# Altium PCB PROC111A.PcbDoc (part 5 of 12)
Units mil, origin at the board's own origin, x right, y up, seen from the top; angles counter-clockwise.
Board outline 7700 x 2300 mil, 6 copper layers (Top Layer, GND 1, SIG 1, SIG 2, GND 2, Bottom Layer), stack 61.062 mil thick; 841 components, 632 nets, 2914 pads, 1627 vias.
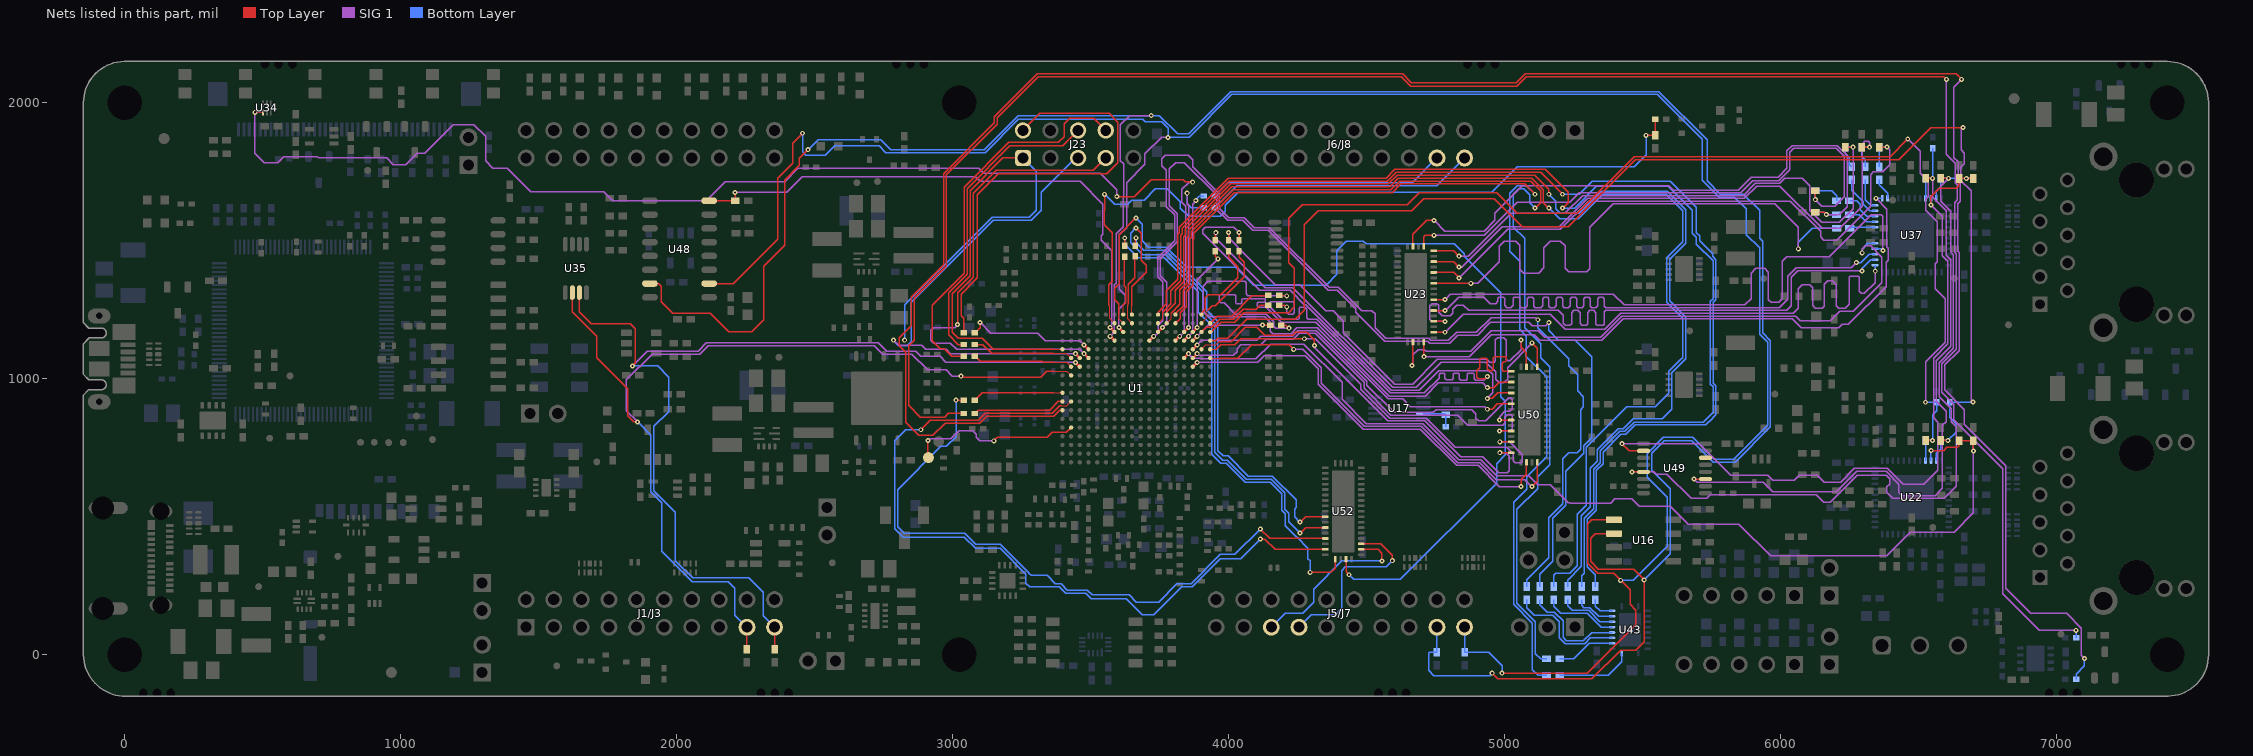
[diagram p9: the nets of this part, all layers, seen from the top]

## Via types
v1: diameter 18, hole 8, Top Layer to Bottom Layer, tented both sides, 1523 vias
v2: diameter 19.68, hole 7.87, Top Layer to Bottom Layer, tented both sides, 104 vias

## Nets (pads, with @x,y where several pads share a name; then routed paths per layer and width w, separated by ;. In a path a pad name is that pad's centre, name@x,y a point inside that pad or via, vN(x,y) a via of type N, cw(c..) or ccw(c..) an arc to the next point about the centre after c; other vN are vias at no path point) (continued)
AM263_EQEP0_A: R328.1 U1.B14 | length 3715.4
  Top Layer w5.3: U1.B14@3806.58,1201.3 3823.55,1218.27 3823.55,1238.81 3845.2,1260.46 3845.2,1314.6 3869.86,1339.27 3869.86,1503.63 3873.69,1507.46 3873.69,1528.02 4019.83,1674.16 4591.58,1674.16 4623.38,1705.96 5072.2,1705.96 v1(5109.51,1668.66)
  Bottom Layer w5.3: v1(5109.51,1668.66) 5078.17,1700 5045,1700 5017.5,1672.5 5017.5,1462 5054.25,1425.25 5054.25,1178.63 5078.38,1154.5 5078.38,1080 5151.68,1006.71 5151.68,717.97 5078.7,645 5078.7,600 5032.22,553.52 5032.22,182.77 5100,114.99 5100,-53.62 5121.38,-75 R328.1@5151.38,-75
AM263_EQEP0_A_R: R328.2 U43.1 | length 277.2
  Bottom Layer w5.3: R328.2@5198.62,-75 5374.13,-75 5424.13,-25 U43.1@5424.13,5.98
AM263_EQEP0_B: R329.1 U1.A14 | length 3726.7
  Top Layer w5.3: U1.A14@3806.58,1232.8 3806.58,1234.99 3834.6,1263.01 3834.6,1318.99 3859.26,1343.66 3859.26,1508.02 3863.09,1511.85 3863.09,1532.41 4015.44,1684.76 4587.18,1684.76 4618.98,1716.56 5093.44,1716.56 5129.38,1680.62 5129.38,1638.54 v1(5109.51,1618.66)
  Bottom Layer w5.3: v1(5109.51,1618.66) 5089.98,1638.18 5089.98,1666.52 5068.32,1688.18 5051.42,1688.18 5031.5,1668.26 5031.5,1549.88 5072.5,1508.88 5072.5,1184.24 5129.52,1127.22 5129.52,1076.22 5162.28,1043.47 5162.28,688.75 5118.53,645 5118.53,602.23 5042.82,526.53 5042.82,187.16 5110.6,119.38 5110.6,116.68 5111.17,116.11 5111.17,3.83 5129.91,-14.91 R329.1@5151.38,-14.91
AM263_EQEP0_B_R: R329.2 U43.3 | length 213.4
  Bottom Layer w5.3: R329.2@5198.62,-14.91 5249.09,-14.91 5305.41,41.41 U43.3@5388.7,41.41
AM263_EQEP0_INDEX: R330.1 U1.D11 | length 3627.9
  Top Layer w10: U1.D11@3712.09,1138.31 v1(3727.84,1154.06)
  SIG 1 w4.75: v1(3727.84,1154.06) 3731.43,1154.06 3736.19,1158.82 3736.38,1158.82 3743.69,1166.13 3743.69,1193.54 3760.09,1209.94 3760.09,1264.29 3760.09,1351.49 3741.88,1369.7 3741.88,1438.9 3803.46,1500.48 3803.46,1594.32 3773.57,1624.21 3773.57,1756.43 3757.97,1772.03 3757.97,1797.66 3769.66,1809.35 3852.94,1809.35 3854.33,1807.96 3868.98,1793.31 3868.98,1768.05 3966.01,1671.01 3966.01,1617.44 3999.54,1583.91 4055.16,1583.91 4091.4,1547.68 4146.89,1547.68 4363.67,1330.91 4396.84,1330.91 4479.55,1248.2 4480.94,1246.81 4507.02,1246.81 cw(c4509.76,1227.76) 4512.51,1246.81 4517.93,1246.81 4519.32,1245.42 4529.81,1234.94 4529.81,1185.4 4568.33,1146.87 4724.31,1146.87 4731.78,1139.4 4795.95,1139.4 4825.26,1168.71 4897.28,1168.71 4950.07,1221.5 5112.15,1221.5 v1(5119.65,1214)
  Bottom Layer w5.3: R330.1@5079.44,247.13 5079.44,271.97 5159.5,352.03 5159.5,496.09 5209.88,546.47 5209.88,710.04 5232.23,732.4 5262.4,732.4 5274.59,744.59 5274.59,887.74 5285,898.15 5285,934.57 5263.5,956.07 5263.5,1015.36 5232.23,1046.63 5232.23,1072.76 5119.65,1185.35 v1(5119.65,1214)
AM263_EQEP0_INDEX_R: R330.2 U43.4 | length 435.2
  Bottom Layer w5.3: R330.2@5079.44,199.89 5079.44,170.8 5107.23,143 5174.19,143 5197.18,120.02 5197.18,62.16 5219.34,40 5289.01,40 5310.1,61.1 U43.4@5388.7,61.1
AM263_EQEP0_STROBE: R331.1 U1.C12 | length 3521.5
  Top Layer w10: U1.C12@3743.59,1169.8 v1(3759.34,1185.55)
  SIG 1 w4.75: v1(3759.34,1185.55) 3775.83,1202.05 3775.83,1349.95 3751.93,1373.86 3751.93,1434.73 3813.51,1496.32 3813.51,1598.48 3784.21,1627.78 3784.21,1760.42 3807.19,1783.4 3839.42,1783.4 3955.96,1666.85 3955.96,1613.28 3995.37,1573.86 4051,1573.86 4087.23,1537.63 4142.73,1537.63 4359.5,1320.86 4392.68,1320.86 4460.15,1253.39 4460.15,1240.84 4564.17,1136.82 4720.15,1136.82 4727.61,1129.35 4800.12,1129.35 4829.43,1158.66 4901.44,1158.66 4947.78,1205 5086.5,1205 5099,1192.5 5148.5,1192.5 v1(5159.5,1203.5)
  Bottom Layer w5.3: R331.1@5127.45,247.13 5127.45,292.72 5172.88,338.15 5172.88,494.48 5220.48,542.08 5220.48,665.42 5285.19,730.14 5285.19,756.89 5315.38,787.08 5315.38,1079.97 5255.35,1140 5194.5,1140 5159.5,1175 v1(5159.5,1203.5)
AM263_EQEP0_STROBE_R: R331.2 U43.5 | length 382
  Bottom Layer w5.3: R331.2@5127.45,199.89 5127.45,181.1 5153.54,155 5180,155 5211.17,123.83 5211.17,63.16 5223.5,50.83 5284.84,50.83 5314.8,80.78 U43.5@5388.7,80.78
AM263_EQEP2_A: R332.1 U1.B13 | length 4081.1
  Top Layer w4: U1.B13@3775.09,1201.3 3790.83,1217.05 3790.83,1237.93
  Top Layer w5.3: 3790.83,1237.93 3822.4,1269.5 3822.4,1321.79 3847.29,1346.68 3847.29,1511.04 3852.49,1516.24 3852.49,1536.8 4011.05,1695.36 4582.79,1695.36 4614.59,1727.16 5097.84,1727.16 5139.98,1685.02 5139.98,1638.18 v1(5159.51,1618.66)
  Bottom Layer w5.3: v1(5159.51,1618.66) 5160.4,1618.66 5199.66,1579.4 5265.42,1579.4 5354.22,1668.2 5584.35,1668.2 5644.52,1608.03 5644.52,1496.1 5586.23,1437.8 5586.23,1277.78 5644.52,1219.49 5644.52,1076.91 5637.86,1070.25 5637.86,1069.97 5594.4,1026.5 5594.4,947.83 5544.68,898.11 5441.4,898.11 5295.79,752.5 5295.79,541.88 5263.06,509.15 5263.06,323.25 5234.78,294.97 5185.01,294.97 5177.45,287.4 R332.1@5177.45,247.13
AM263_EQEP2_A_R: R332.2 U43.6 | length 266.9
  Bottom Layer w5.3: R332.2@5177.45,199.89 5177.45,175.16 5202.6,150 5299.54,150 5349.07,100.47 U43.6@5388.7,100.47
AM263_EQEP2_B: R333.1 U1.A13 | length 4039
  Top Layer w4: U1.A13@3775.09,1232.8 3775.09,1242.08
  Top Layer w5.3: 3775.09,1242.08 3806.58,1273.58 3806.58,1320.96 3836.69,1351.07 3836.69,1515.43 3841.89,1520.63 3841.89,1541.2 4006.66,1705.96 4578.4,1705.96 4610.2,1737.76 5108.54,1737.76 5159.51,1686.79 v1(5159.51,1668.66)
  Bottom Layer w5.3: v1(5159.51,1668.66) 5185,1643.17 5185,1615.56 5201.42,1599.14 5270.16,1599.14 5349.83,1678.8 5588.74,1678.8 5655.12,1612.42 5655.12,1491.71 5596.83,1433.41 5596.83,1282.17 5655.12,1223.88 5655.12,1072.24 5605,1022.11 5605,888.76 5571.24,855 5464.98,855 5429.67,819.69 5411.6,819.69 5334.84,742.93 5334.84,700.53 5310,675.69 5310,536.96 5276.85,503.81 5276.85,319.93 5227.45,270.52 R333.1@5227.45,247.13
AM263_EQEP2_B_R: R333.2 U43.7 | length 207.4
  Bottom Layer w5.3: R333.2@5227.45,199.89 5227.45,177.55 5244.4,160.6 5303.93,160.6 5344.38,120.15 U43.7@5388.7,120.15
AM263_EQEP2_INDEX: R334.1 U1.A12 | length 4240.1
  Top Layer w5.3: U1.A12@3743.59,1232.8 3743.59,1241.19 3773.85,1271.45 3773.85,1318.2 3815.49,1359.85 3815.49,1524.21 3820.69,1529.41 3820.69,1549.98 3997.88,1727.16 4569.62,1727.16 4601.42,1758.96 5146.81,1758.96 5229.48,1676.3 5229.48,1638.63 v1(5209.51,1618.66)
  Bottom Layer w5.3: v1(5209.51,1618.66) 5252.86,1618.66 5331.51,1697.31 5592.69,1697.31 5680,1610 5680,1526.8 5694.52,1512.28 5694.52,1487.83 5754.52,1427.83 5754.52,1290.9 5745.28,1281.66 5745.28,979.8 5754.52,970.56 5754.52,878.84 5719.05,843.37 5468.34,843.37 5434.06,809.09 5415.99,809.09 5345.44,738.54 5345.44,696.14 5321.45,672.15 5321.45,528.97 5287.45,494.97 5287.45,296.35 5278.06,286.97 R334.1@5278.06,247.13
AM263_EQEP2_INDEX_R: R334.2 U43.8 | length 147.2
  Bottom Layer w5.3: R334.2@5278.06,199.89 5278.06,180 5286.86,171.2 5308.32,171.2 5339.68,139.84 U43.8@5388.7,139.84
AM263_EQEP2_STROBE: R335.1 U1.B12 | length 4195.6
  Top Layer w4: U1.B12@3743.59,1201.3 3760,1217.71 3760,1235
  Top Layer w5.3: 3760,1235 3760,1241.99 3790,1271.99 3790,1319.37 3826.09,1355.46 3826.09,1519.82 3831.29,1525.02 3831.29,1545.59 4002.27,1716.56 4574.01,1716.56 4605.81,1748.36 5129.8,1748.36 v1(5209.51,1668.66)
  Bottom Layer w5.3: v1(5209.51,1668.66) 5270.14,1668.66 5316.48,1715 5600,1715 5693.5,1621.5 5693.5,1529.5 5705.48,1517.52 5705.48,1500.65 5753.33,1452.8 5753.33,1444.01 5765.12,1432.22 5765.12,1286.51 5755.88,1277.27 5755.88,984.19 5765.12,974.95 5765.12,869.89 5753.33,858.1 5753.33,857.79 5728.31,832.77 5472.73,832.77 5438.45,798.49 5420.38,798.49 5356.04,734.15 5356.04,691.75 5332.05,667.76 5332.05,524.58 5298.05,490.58 5298.05,319.67 5328.01,289.71 R335.1@5328.01,247.13
AM263_EQEP2_STROBE_R: R335.2 U43.9 | length 91.1
  Bottom Layer w5.3: R335.2@5328.01,199.89 5328.01,176.51 5345,159.52 U43.9@5388.7,159.52
AM263_EXT_REFCLK0: TP2.1 U1.P2 | length 637.5
  Top Layer w5.3: v1(2910,776.1) 2910,716.22 TP2.1@2911.79,714.43 ; v1(3148.62,775.4) 3161.89,788.67 3343.09,788.67 3360.79,806.37 3411.66,806.37 U1.P2@3428.63,823.35
  SIG 1 w5.3: v1(2910,776.1) 2915.9,782 2993.46,782 3022.83,811.37 3073.09,811.37 3084.52,799.94 3084.52,787.86 3096.99,775.4 v1(3148.62,775.4)
AM263_FSIRX1_CLK: J23.1 U1.E1 | length 2160.2
  Top Layer w4: 3365.64,1106.81 U1.E1@3397.13,1106.81
  Top Layer w5.3: J23.1@3254.17,1800 3181,1800 3063,1682 3063,1374 2997.98,1308.98 2997.98,1169.46 3020.54,1146.89 3105.82,1146.89 3145.9,1106.81 3365.64,1106.81
  Bottom Layer w5.3: v1(2825.61,1140) 2826.32,1140.71 2826.32,1268.09 3143.73,1585.5 3277.61,1585.5 3302.05,1609.94 3302.05,1752.13 J23.1@3254.17,1800
AM263_FSIRX1_DATA0: J23.5 U1.F3 | length 1782.6
  Top Layer w10: v1(3444.38,1091.06) U1.F3@3460.12,1075.32
  SIG 1 w4.75: v1(2785,1140) 2803.56,1121.44 2816.94,1121.44 2817.63,1120.75 2888.25,1120.75 2902.5,1106.5 2975.39,1106.5 2990.82,1091.06 v1(3444.38,1091.06)
  Bottom Layer w5.3: v1(2785,1140) 2805,1120 2835,1120 2850,1135 2850,1276.78 3147.22,1574 3284,1574 3320,1610 3320,1675.78 3437.73,1793.5 3447.67,1793.5 J23.5@3454.17,1800
AM263_FSIRX1_DATA1: J23.7 U1.F4 | length 1770.2
  Top Layer w5.3: v1(3017.5,1197) 3017.5,1311.5 3073.6,1367.6 3073.6,1672 3157.1,1755.5 3509.67,1755.5 J23.7@3554.17,1800
  Top Layer w10: v1(3475.87,1091.06) U1.F4@3491.62,1075.32
  SIG 1 w4.75: v1(3017.5,1197) 3006.21,1185.71 2931.21,1185.71 2921,1175.5 2921,1140 2931.5,1129.5 2991,1129.5 3014.06,1106.44 3460.5,1106.44 v1(3475.87,1091.06)
AM263_FSITX1_CLK: J23.2 R54.1 | length 1615.8
  Top Layer w5.3: R54.1@3040,1167.26 3040,1219 3030,1229 3030,1306.5 3089,1365.5 3089,1667.6 3164.9,1743.5 3558.49,1743.5 3598.5,1783.5 3598.5,1930 3567,1961.5 3315.67,1961.5 J23.2@3254.17,1900
AM263_FSITX1_CLK_R: R54.2 U1.E4 | length 480.3
  Top Layer w5.3: R54.2@3079.37,1167.26 3081.34,1167.26 3099,1184.92 v1(3099,1204.5)
  Top Layer w10: v1(3475.87,1122.56) U1.E4@3491.62,1106.81
  SIG 1 w4.75: v1(3099,1204.5) 3138,1165.5 3308.5,1165.5 3335.5,1138.5 3366.64,1138.5 3459.93,1138.5 3475.37,1123.06 v1@3476.77,1123.06
AM263_FSITX1_DATA0: J23.6 R57.1 | length 1115.8
  Top Layer w5.3: R57.1@3040,1124.26 3020.24,1124.26 2985.36,1159.14 2985.36,1311.35 3052.4,1378.39 3052.4,1688.9 3207,1843.5 3397.67,1843.5 J23.6@3454.17,1900
AM263_FSITX1_DATA0_R: R57.2 U1.F2 | length 369.5
  Top Layer w4: 3365.64,1092.05 3411.9,1092.05 U1.F2@3428.63,1075.32
  Top Layer w5.3: R57.2@3079.37,1124.26 3108.74,1124.26 3140.95,1092.05 3365.64,1092.05
AM263_FSITX1_DATA1: J23.8 R58.1 | length 1404.9
  Top Layer w5.3: R58.1@3040,1081.26 2995.39,1081.26 2968.16,1108.5 2954.44,1108.5 2925.16,1137.78 2925.16,1266.14 3040.7,1381.68 3040.7,1694.2 3203,1856.5 3382,1856.5 3403,1877.5 3403,1924 3423,1944 3510.17,1944 J23.8@3554.17,1900
AM263_FSITX1_DATA1_R: R58.2 U1.G2 | length 364.8
  Top Layer w4: 3365.64,1059.57 3412.88,1059.57 U1.G2@3428.63,1043.82
  Top Layer w5.3: R58.2@3079.37,1081.26 3081.74,1081.26 3099.78,1063.22 3323.21,1063.22 3326.87,1059.57 3365.64,1059.57
AM263_I2C1_SCL: J5/J7.49 R175.1 U1.D7 U16.6 U48.15 | length 9567.8
  Top Layer w5.3: U48.15@1902.72,1345 1934.14,1345 1943.57,1335.56 1943.57,1279.46 1985.7,1237.34 2121.11,1237.34 2188.06,1170.38 2271.5,1170.38 2315,1213.89 2315,1407.62 2390.58,1483.2 2390.58,1720.21 2444.07,1773.69 2444.07,1799.07 v1(2475,1830) ; v1(4954.31,-66.61) 4974.89,-87.19 5315.28,-87.19 5419.6,17.13 5474.03,17.13 5505,48.1 v1(5505,271.38) 5466.38,310 5338.71,310 5310.6,338.11 5310.6,421.98 5327.76,439.14 U16.6@5395.51,439.14
  Top Layer w10: v1(3570.36,1154.06) U1.D7@3586.11,1138.31
  SIG 1 w4.75: v1(3570.36,1154.06) 3585.74,1169.43 3585.74,1340.93 3591.68,1346.88 3591.68,1525.98 3617.42,1551.72 3617.42,1658.33 3619.25,1660.16 3619.25,1778.67 3607.21,1790.71 3607.21,1920.01 3640.95,1953.74 v1(3719.04,1953.74)
  Bottom Layer w5.3: v1(2475,1830) 2475.54,1830 2512.35,1866.81 2738.69,1866.81 2774.99,1830.51 3113.05,1830.51 3236.28,1953.74 3713.17,1953.74 3715.96,1950.96 3715.96,1950.65 v1(3719.04,1953.74) 3748.66,1953.74 3814.31,1888.09 3854.25,1888.09 4006.88,2040.72 5557.48,2040.72 5732.72,1865.49 5732.72,1717.28 5780.85,1669.15 5781.86,1669.15 5863.61,1669.14 5922.85,1609.89 5922.85,1509.68 5933.8,1498.73 5933.8,1166.2 5962.62,1137.38 5962.62,826.63 5834.47,698.48 5755.04,698.48 5677.42,776.1 5578.23,776.1 5532.27,730.14 5532.27,669.31 5599.4,602.17 5599.4,365.78 v1(5505,271.38) ; J5/J7.49@4754.17,100 4754.17,10.51 R175.1@4753.31,9.65 4727.33,9.65 4723.66,5.98 4723.66,-56.53 4742.67,-75.54 4944.86,-75.54 4953.78,-66.61 v1(4954.31,-66.61)
AM263_I2C1_SDA: J5/J7.50 R176.1 U1.C8 U16.5 U48.2 | length 8836.2
  Top Layer w5.3: U48.2@2117.28,1345 2203.98,1345 2365,1506.02 2365,1725.92 2419.22,1780.14 2419.22,1853.42 v1(2455.48,1889.68) ; v1(4990,-66.61) 5298.13,-66.61 5474.03,109.28 5474.03,162.18 5453.66,182.55 5453.66,236.34 v1(5420,270) 5395,295 5336.14,295 5300,331.14 5300,475 5314.14,489.14 U16.5@5395.51,489.14
  Top Layer w10: v1(3601.86,1185.55) U1.C8@3617.61,1169.8
  SIG 1 w4: v1(3601.86,1185.55) v1@3602.45,1186.14
  SIG 1 w4.75: v1@3601.29,1187.29 3601.86,1187.86 3601.86,1251.8 3625.62,1275.57 3625.62,1303.13 3603.75,1325 3603.75,1522.05 3629.73,1548.03 3629.73,1710.68 3696.35,1777.3 3696.35,1814.55 3756.55,1874.75 v1(3780,1874.75)
  Bottom Layer w5.3: v1(2455.48,1889.68) 2455.48,1838.09 2455.48,1821.91 2466.91,1810.48 2538.63,1810.48 2572.09,1843.93 2732.81,1843.93 2756.93,1819.81 2770.87,1819.81 ; 2770.87,1819.91 3117.44,1819.91 3237.58,1940.05 3688.15,1940.05 3697.69,1930.51 3756.7,1930.51 3780,1907.21 v1(3780,1874.75) 3855.9,1874.75 4011.27,2030.12 5553.09,2030.12 5715,1868.21 5715,1720.01 5776.47,1658.54 5832.02,1658.54 5875,1615.56 5875,1522.52 5923.2,1474.32 5923.2,1161.78 5952.02,1132.96 5952.02,831.02 5830.08,709.08 5759.44,709.08 5680.92,787.6 5574.74,787.6 5515.6,728.46 5515.6,643.26 5588.8,570.06 5588.8,393.9 5464.9,270 v1(5420,270) ; J5/J7.50@4854.17,100 R176.1@4854.17,9.65 4940.97,9.65 4990,-39.38 v1(4990,-66.61)
AM263_I2C3_SCL: J1/J3.9 R55.1 U1.H2 U35.2 | length 3534.8
  Top Layer w4: 3365.64,1027.69 3413.27,1027.69 U1.H2@3428.63,1012.32
  Top Layer w5.3: U35.2@1621.58,1312.4 1621.58,1242.87 1710,1154.45 1710,1076.21 1822.4,963.81 1822.4,865.62 1844.17,843.85 1845.98,843.85 1846.13,843.7 v1(1857.95,843.7) ; R55.1@2254.17,20 J1/J3.9@2254.17,100 ; v1(3030,1009.39) 3034.39,1005 3318.45,1005 3341.13,1027.69 3365.64,1027.69
  SIG 1 w4.75: v1(1857.95,843.7) 1817.11,884.54 1817.11,996.3 1910.3,1089.49 2083.05,1089.49 2113.97,1120.41 2714.95,1120.41 2746.36,1089 2852,1089 2909,1032 2976.24,1032 2998.86,1009.39 v1(3030,1009.39)
  Bottom Layer w5.3: v1(1857.95,843.7) 1905.85,795.8 1905.85,590.43 1944.9,551.39 1944.9,375.58 2055.48,265 2185.85,265 2210,240.85 2210,144.17 J1/J3.9@2254.17,100
AM263_I2C3_SDA: J1/J3.10 R56.1 U1.G3 U35.3 | length 3582.2
  Top Layer w5.3: U35.3@1647.17,1312.4 1647.17,1242.83 1690,1200 1830.45,1200 1849.67,1180.78 1849.67,1056.08 v1(1840,1046.41) ; R56.1@2354.17,20 J1/J3.10@2354.17,100
  Top Layer w10: v1(3444.38,1059.57) U1.G3@3460.12,1043.82
  SIG 1 w4.75: v1(1840,1046.41) 1893.74,1100.15 2077.14,1100.15 2107.45,1130.46 2729.35,1130.46 2759.85,1099.95 2865.1,1099.95 2884.05,1081 2954,1081 2974.42,1060.58 3443.37,1060.58 v1(3444.38,1059.57)
  Bottom Layer w5.3: v1(1840,1046.41) 1930.2,1046.41 1970.2,1006.41 1970.2,881.38 1917.39,828.57 1917.39,593.89 1995,516.27 1995,341.36 2057.95,278.41 2261.59,278.41 2313.14,226.86 2313.14,141.04 J1/J3.10@2354.17,100
AM263_ICSSM_MII0_COL: R207.1 R219.2 R231.2 U37.45 U49.11 | length 2483
  Top Layer w5.3: v1(5685,636.84) U49.11@5727.2,636.84 ; R207.1@6524.39,1726.46 v1(6550,1726.46)
  SIG 1 w4.75: v1(5685,636.84) 5697.47,624.38 5936.37,624.38 5970.75,590 6154.59,590 6155.65,591.06 6200.52,591.06 6274.46,665 6381.49,665 6428.11,618.37 6428.11,588.69 6439.88,576.92 6560,576.92 6585.75,602.67 6585.75,831.83 6598.64,844.71 6598.64,883.27 6563.34,918.57 6563.34,1065.64 6615.6,1117.91 6615.6,1430.48 6598.64,1447.44 6598.64,1609.67 6550,1658.31 v1(6550,1726.46)
  Bottom Layer w5.3: U37.45@6524.39,1653.9 6524.52,1654.03 6524.52,1726.32 R219.2@6524.39,1726.46 v1(6550,1726.46) R231.2@6550,1835
AM263_ICSSM_MII0_CRS: U49.14
AM263_ICSSM_MII0_RXCLK: R196.1 U23.32 | length 2186.3
  Top Layer w5.3: U23.32@4742.17,1345.87 v1(4876.97,1345.87)
  SIG 1 w4.75: v1(4876.97,1345.87) 4902.52,1345.87 4980,1423.35 4980,1480 4998.88,1498.88 5040,1498.88 5055,1483.88 5055,1397.01 5068.7,1383.31 5122.43,1383.31 5140.93,1401.81 5140.93,1475.68 5164.12,1498.88 5201.12,1498.88 5218.7,1481.3 5218.7,1400.78 5231.13,1388.35 5297.26,1388.35 5308.38,1399.47 5308.38,1549.63 5392.5,1633.75 5978.06,1633.75 6063.36,1548.45 v1(6063.36,1470.91)
  Bottom Layer w5.3: v1(6063.36,1470.91) 6063.36,1494.73 6113.67,1545.04 R196.1@6201.89,1545.04
AM263_ICSSM_MII0_RXCLK_R: R196.2 U37.32 | length 94.1
  Bottom Layer w5.3: R196.2@6249.14,1545.04 6253.66,1549.57 U37.32@6341.32,1549.57
AM263_ICSSM_MII0_RXD0: R198.1 R203.1 R215.2 U23.41 | length 2259.9
  Top Layer w5.3: U23.41@4667.36,1479.73 4667.36,1524.62 4716.61,1573.86 v1(4743.56,1573.86) ; R203.1@6125,1602.65 6157.35,1602.65 v1(6165,1595)
  SIG 1 w4.75: v1(4743.56,1573.86) 4782.42,1535 4925.67,1535 4964.25,1573.58 4964.25,1600.62 5063.63,1700 5593.81,1700 5609.81,1684 5846.48,1684 5892.48,1730 5990,1730 6022.02,1762.02 6022.02,1826.07 6040.95,1845 6204.95,1845 6240,1809.95 6240,1623.91 6211.09,1595 v1(6165,1595)
  Bottom Layer w5.3: R215.2@6124.92,1602.65 6155.55,1602.65 6163.2,1595 v1(6165,1595) v1(6165,1595) R198.1@6201.89,1595.04
AM263_ICSSM_MII0_RXD0_R: R198.2 U37.33 | length 102.9
  Bottom Layer w5.3: R198.2@6249.14,1595.04 6284.21,1595.04 6310,1569.25 U37.33@6341.32,1569.25
AM263_ICSSM_MII0_RXD1: R199.1 R204.1 R216.2 U23.39 | length 2182.3
  Top Layer w5.3: U23.39@4706.73,1479.73 4706.73,1514.99 4711.74,1520 v1(4743.56,1520) ; v1(6124.92,1648.96) 6125,1649.04 R204.1@6125,1680.96
  SIG 1 w4.75: v1(4743.56,1520) 4924.88,1520 5045.38,1640.5 5236.09,1640.5 5269.54,1673.95 5854.95,1673.95 5899.09,1718.09 5992.3,1718.09 6032.07,1757.86 6032.07,1820.68 6046.35,1834.95 6200.79,1834.95 6229.95,1805.79 6229.95,1659.66 6195.29,1625 6148.88,1625 v1(6124.92,1648.96)
  Bottom Layer w5.3: v1(6124.92,1648.96) 6125,1649.04 R216.2@6125,1680.96 6125.11,1680.85 6185,1680.85 6201.89,1663.96 R199.1@6201.89,1645.04
AM263_ICSSM_MII0_RXD1_R: R199.2 U37.34 | length 126.8
  Bottom Layer w5.3: R199.2@6249.14,1645.04 6249.18,1645 6275.16,1645 6288.01,1632.15 6288.01,1612.74 6311.81,1588.94 U37.34@6341.32,1588.94
AM263_ICSSM_MII0_RXD2: R200.1 R210.1 R222.2 U23.38 | length 2143.2
  Top Layer w5.3: U23.38@4742.17,1463.98 4814.13,1463.98 v1(4833.82,1444.29) ; R210.1@6233.01,1839.35 6261.65,1839.35 v1(6261.73,1839.27)
  SIG 1 w4.75: v1(4833.82,1444.29) 4868.16,1444.29 5023.28,1599.41 5217.48,1599.41 5281.97,1663.9 5863.95,1663.9 5908.09,1708.04 5996.47,1708.04 6015.12,1726.69 6078.31,1726.69 6105.67,1699.33 6105.67,1610.83 6148.88,1567.62 6212.62,1567.62 6261.73,1616.73 v1(6261.73,1839.27)
  Bottom Layer w5.3: R200.1@6256.28,1768.62 6247.12,1777.78 6247.12,1800.5 6233.01,1814.61 R222.2@6233.01,1839.35 6261.65,1839.35 v1(6261.73,1839.27)
AM263_ICSSM_MII0_RXD2_R: R200.2 U37.35 | length 159.3
  Bottom Layer w5.3: R200.2@6256.28,1721.38 6256.28,1683.72 6298.61,1641.39 6298.61,1631.98 6321.97,1608.62 U37.35@6341.32,1608.62
AM263_ICSSM_MII0_RXD3: R201.1 R211.1 R223.2 U23.36 | length 2186
  Top Layer w5.3: U23.36@4742.17,1424.61 4814.13,1424.61 v1(4833.82,1404.92) ; R211.1@6293.01,1839.35 v1(6321.73,1839.27) v1(6321.73,1839.27)
  SIG 1 w4.75: v1(4833.82,1404.92) 4844.92,1404.92 4991.14,1551.14 5197.63,1551.14 5300.34,1653.85 5868.14,1653.85 5912.28,1697.99 5997.02,1697.99 6150.01,1545 6214.04,1545 6294.47,1625.43 6294.47,1849.47 6305,1860 6317.22,1860 6321.73,1855.49 v1(6321.73,1839.27)
  Bottom Layer w5.3: R201.1@6306.28,1768.62 6306.28,1793.72 6293.01,1806.99 R223.2@6293.01,1839.35 v1(6321.73,1839.27) v1(6321.73,1839.27)
AM263_ICSSM_MII0_RXD3_R: R201.2 U37.36 | length 116.2
  Bottom Layer w5.3: R201.2@6306.28,1721.38 6306.28,1648.71 6326.68,1628.31 U37.36@6341.32,1628.31
AM263_ICSSM_MII0_RXDV: R197.1 R205.1 R217.2 U23.34 | length 2223.6
  Top Layer w5.3: U23.34@4742.17,1385.24 4814.74,1385.24 v1(4834.43,1365.55) ; R205.1@6356.28,1839.43 6384.92,1839.43 v1(6385,1839.35)
  SIG 1 w4.75: v1(4834.43,1365.55) 5009.93,1541.06 5201.76,1541.06 5304.5,1643.8 6035.09,1643.8 6144.37,1534.51 6144.37,1513.83 6155.65,1502.56 6202.8,1502.56 6325.75,1625.51 6325.75,1740 6335.75,1750 6370,1750 6395,1775 6395,1829.35 v1(6385,1839.35)
  Bottom Layer w5.3: R197.1@6356.28,1768.62 R217.2@6356.28,1839.43 6384.92,1839.43 v1(6385,1839.35)
AM263_ICSSM_MII0_RXDV_R: R197.2 U37.38 | length 80
  Bottom Layer w5.3: R197.2@6356.28,1721.38 6356.28,1702.66 6386.59,1672.35 U37.38@6386.59,1653.9
AM263_ICSSM_MII0_RXER: R206.1 R218.2 R235.2 U37.46 U49.2 | length 2661.3
  Top Layer w5.3: v1(5424.59,764.8) 5450.18,739.2 U49.2@5502.8,739.2 ; v1(6544.07,1629.98) 6544.07,1660.03 6574.04,1690 6635,1690 6645,1700 6645,1724.79 R206.1@6646.28,1726.06 v1(6672.14,1726.06) R218.2@6698,1726.06
  SIG 1 w4.75: v1(5424.59,764.8) 5704.89,764.8 5818.34,651.34 5952.83,651.34 5970.87,633.3 6049.35,633.3 6066.09,650.03 6132.75,650.03 6157.03,625.75 6217.49,625.75 6266.79,675.05 6385.65,675.05 6443.6,617.1 6517.1,617.1 6569.25,669.25 6569.25,842.92 6553.29,858.88 6553.29,1074.29 6605.55,1126.55 6605.55,1426.31 6585.75,1446.11 6585.75,1588.3 v1(6544.07,1629.98)
  Bottom Layer w5.3: v1(6544.07,1629.98) U37.46@6544.07,1653.9 ; v1(6672.14,1726.06) 6672.77,1726.69 R235.2@6698,1726.69
AM263_ICSSM_MII0_RXLINK: R208.1 R220.2 R233.2 U37.47 U49.5 | length 2777.1
  Top Layer w5.3: v1(5460.59,662.43) U49.5@5502.8,662.43 ; R208.1@6579.39,1726.46 v1(6608,1726.46)
  SIG 1 w4.75: v1(5460.59,662.43) 5539.53,662.43 5547.98,653.98 5587.42,653.98 5674.99,566.41 5731.68,566.41 5745.21,579.95 6128.26,579.95 6155.65,552.56 6179.24,552.56 6277.29,650.6 6381.62,650.6 6394.25,637.97 6394.25,618.34 6384.22,608.31 6384.22,588.69 6406.04,566.87 6591.87,566.87 6635,610 6635,825.92 6616.98,843.94 6616.98,891.66 6573.39,935.25 6573.39,1058.39 6625.65,1110.65 6625.65,1449.53 6615,1460.18 6615,1607.52 6580,1642.52 6580,1698.46 v1(6608,1726.46)
  Bottom Layer w5.3: U37.47@6563.76,1653.9 6563.76,1679.37 6579.39,1695 R220.2@6579.39,1726.46 v1(6608,1726.46) 6644.76,1726.46 R233.2@6645,1726.69
AM263_ICSSM_MII0_TXCLK: U23.19 U37.29 | length 2239
  Top Layer w5.3: v1(4664.29,1048.46) 4664.29,1051.89 4667.36,1054.97 U23.19@4667.36,1133.27
  SIG 1 w4.75: v1(4664.29,1048.46) 4666.82,1050.99 4666.82,1087.26 4685.53,1105.97 4708.36,1105.97 4715.13,1099.2 4876.48,1099.2 4950.59,1173.32 5121.68,1173.32 5145,1150 5347.08,1150 5424.45,1227.37 6053.73,1227.37 6071,1210.1 6179.33,1210.1 6214.23,1245 6262.71,1245 6366.08,1348.37 6366.08,1440.42 6325.07,1481.43 6306.81,1481.43 6295.08,1469.7 6295.08,1456.56 v1(6295,1456.47)
  Bottom Layer w5.3: v1(6295,1456.47) 6295,1469.87 6315.64,1490.51 U37.29@6341.32,1490.51
AM263_ICSSM_MII0_TXD0: U23.29 U37.28 | length 2238.6
  Top Layer w5.3: U23.29@4742.17,1286.81 v1(4783.82,1286.81)
  SIG 1 w4.75: v1(4783.82,1286.81) 4803.26,1306.25 5393.75,1306.25 5432.43,1267.57 5870,1267.57 5893.31,1290.89 5893.31,1383.31 5910,1400 5940.94,1400 5954.93,1386.01 5954.93,1287.02 5964.98,1276.97 5991.97,1276.97 6005,1290 6005,1425.32 6022.02,1442.34 6175.23,1442.34 6327.9,1595 6364.23,1595 6370,1589.23 v1(6370,1465)
  Bottom Layer w5.3: U37.28@6341.32,1470.83 6364.17,1470.83 v1(6370,1465)
AM263_ICSSM_MII0_TXD1: U23.27 U37.27 | length 2238.5
  Top Layer w5.3: U23.27@4742.17,1247.44 v1(4783.82,1247.44)
  SIG 1 w4.75: v1(4783.82,1247.44) 4832.58,1296.2 4923.64,1296.2 4947.17,1272.67 4966.6,1272.67 4975,1281.08 4975,1291.2 4980,1296.2 4995.03,1296.2 5000,1291.23 5000,1265.63 5007.93,1257.7 5021.95,1257.7 5030,1265.76 5030,1291.63 5034.57,1296.2 5050,1296.2 5054.29,1291.91 5054.29,1263.41 5060,1257.7 5075,1257.7 5081.71,1264.41 5081.71,1289.62 5087.09,1295 5100,1295 5105,1290 5105,1262.7 5110,1257.7 5130,1257.7 5136.71,1264.41 5136.71,1289.62 5142.09,1295 5155,1295 5160,1290 5160,1262.7 5165,1257.7 5180,1257.7 5186.71,1264.41 5186.71,1289.62 5192.09,1295 5205,1295 5210,1290 5210,1262.7 5215,1257.7 5230,1257.7 5236.71,1264.41 5236.71,1289.62 5242.09,1295 5255,1295 5260,1290 5260,1262.7 5265,1257.7 5280,1257.7 5286.71,1264.41 5286.71,1289.62 5292.09,1295 5305,1295 5310,1290 5310,1262.7 5315,1257.7 5330,1257.7 5336.71,1264.41 5336.71,1289.62 5342.09,1295 5355,1295 5360,1290 5360,1262.7 5365.18,1257.52 5995,1257.52 6025,1287.52 6025,1370.85 6056.45,1402.3 6254.57,1402.3 v1(6273.51,1421.24)
  Bottom Layer w5.3: v1(6273.51,1421.24) 6289.75,1421.24 6319.65,1451.14 U37.27@6341.32,1451.14
AM263_ICSSM_MII0_TXD2: U23.25 U37.26 | length 2245.1
  Top Layer w5.3: U23.25@4742.17,1208.07 v1(4783.82,1208.07)
  SIG 1 w4.75: v1(4783.82,1208.07) 4735,1208.07 4727.81,1215.27 4727.81,1263.87 4736.61,1272.67 4753.59,1272.67 4760,1266.26 4760,1241.44 4773.24,1228.19 4802.19,1228.19 4811,1237 4811,1251.85 4825.85,1266.69 4849.73,1266.69 4868.95,1247.47 5193.6,1247.47 5211.5,1229.57 5211.5,1201.08 5219.16,1193.42 5235.21,1193.42 5241.78,1199.99 5241.78,1239.25 5250,1247.47 5265,1247.47 5272.49,1239.98 5272.49,1200.49 5278.06,1194.92 5295.48,1194.92 5300,1199.43 5300,1240 5307.47,1247.47 5322.53,1247.47 5330,1240 5330,1198.38 5334.96,1193.42 5356.27,1193.42 5360,1197.15 5360,1242.47 5365,1247.47 6021.47,1247.47 6037.84,1263.84 6037.84,1367.25 6061.44,1390.85 v1(6294.47,1390.85)
  Bottom Layer w5.3: v1(6294.47,1390.85) 6294.47,1400.71 6325.21,1431.46 U37.26@6341.32,1431.46
AM263_ICSSM_MII0_TXD3: U23.23 U37.25 | length 2244.1
  Top Layer w5.3: U23.23@4742.17,1168.7 v1(4783.82,1168.7)
  SIG 1 w4.75: v1(4783.82,1168.7) 4849.46,1234.35 5164.02,1234.35 5219,1179.37 5362.23,1179.37 5420.29,1237.42 6045,1237.42 6063.36,1255.78 6063.36,1325.71 6077.65,1340 6104.55,1340 6115,1329.55 6115,1265.76 6125.11,1255.64 6150.52,1255.64 6157.97,1263.09 6157.97,1343.37 6170.6,1356 6186.86,1356 6201.36,1341.5 6201.36,1265.04 6210.4,1256 6233.17,1256 6247.17,1270 6247.17,1367.17 6251,1371 6280.92,1371 6284.76,1367.16 6284.76,1316.56 6292.03,1309.28 6302.69,1309.28 6342.17,1348.76 v1(6342.17,1390)
  Bottom Layer w5.3: U37.25@6341.32,1411.77 6341.32,1390.85 v1(6342.17,1390)
AM263_ICSSM_MII0_TXEN: U23.21 U37.37 | length 2239.7
  Top Layer w5.3: U23.21@4706.73,1133.27 4706.73,1080.38 v1(4707.11,1080)
  SIG 1 w4.75: v1(4707.11,1080) 4871.49,1080 4951.48,1159.99 5107.38,1159.99 5127.42,1139.95 5351.24,1139.95 5428.61,1217.32 6040.85,1217.32 6073.21,1184.96 6210.2,1184.96 6223.06,1197.82 6245.09,1197.82 6381.62,1334.35 6381.62,1422.37 6389.25,1430 6389.25,1472.97 6384.22,1478 6384.22,1614.68 v1(6345,1653.9)
  Bottom Layer w5.3: v1(6345,1653.9) U37.37@6366.91,1653.9
AM263_ICSSM_MII1_COL: R112.1 R124.2 R225.2 U1.C18 U22.45 | length 4456.8
  Top Layer w5.3: U1.C18@3932.57,1169.8 3936.6,1169.8 3972.5,1205.7 4020.68,1205.7 4054.8,1239.82 4216.67,1239.82 4237.19,1260.33 4237.19,1400.12 4217.66,1419.64 4217.66,1581.16 4266.75,1630.25 4646.75,1630.25 4690.66,1674.16 4969.95,1674.16 5044.97,1599.14 5262.42,1599.14 5468.28,1805 6395.79,1805 v1(6460,1869.21) ; R112.1@6524.39,776.46 v1(6550,776.46)
  SIG 1 w4.75: v1(6460,1869.21) 6505.14,1824.08 6505.14,1744.1 6534.3,1714.93 6534.3,1659.3 6524.82,1649.82 6524.82,1610.85 6566.13,1569.54 6566.13,1423.87 6560,1417.73 6560,1325.5 6595.5,1290 6595.5,1132.11 6524.39,1061 v1(6524.39,915)
  Bottom Layer w5.3: U22.45@6524.39,703.9 6524.52,704.03 6524.52,776.32 R124.2@6524.39,776.46 v1(6550,776.46) 6550,870 6565,885 R225.2@6565,914.94 6524.45,914.94 v1(6524.39,915)
AM263_ICSSM_MII1_RXCLK: U1.E16 U50.31 | length 1530.3
  Top Layer w5.3: v1(4981.16,850.35) U50.31@5023.43,850.35
  Top Layer w10: U1.E16@3869.57,1106.81 v1(3885.32,1122.56)
  SIG 1 w4.75: v1(3885.32,1122.56) 3901.82,1139.06 4100.66,1139.06 4115.61,1154 4229.88,1154 4250.29,1174.4 4316.88,1174.4 4500,991.28 4500,977.38 4599.39,877.99 4741.44,877.99 4751.66,888.21 4879.44,888.21 4895,872.66 4895,857.89 4905.05,847.84 4930.12,847.84 5013.56,931.29 5020.68,931.29 5027.73,924.24 5027.73,891.58 5018.72,882.57 5000.46,882.57 4981.16,863.27 v1(4981.16,850.35)
AM263_ICSSM_MII1_RXD0: U1.F18 U50.42 | length 1527.9
  Top Layer w4: U1.F18@3932.57,1075.32 3963.77,1075.32 3964.06,1075.03
  Top Layer w5.3: 3964.06,1075.03 3965.16,1073.93 4032.78,1073.93 4082.43,1123.58 4218.23,1123.58 v1(4234.99,1106.82) ; v1(5098.23,609.55) 5117.91,629.23 U50.42@5117.91,696.81
  SIG 1 w4.75: v1(4234.99,1106.82) 4267.5,1106.82 4334.56,1039.75 4334.56,983.75 4490.56,827.74 4697.67,827.74 4829.44,695.97 4908.54,695.97 4969.51,635 5072.77,635 v1(5098.23,609.55)
AM263_ICSSM_MII1_RXD1: U1.G16 U50.40 | length 1530
  Top Layer w5.3: v1(5058.86,609.55) 5058.86,635.31 5078.54,655 U50.40@5078.54,696.81
  Top Layer w10: U1.G16@3869.57,1043.82 v1(3885.32,1059.57)
  SIG 1 w4.75: v1(3885.32,1059.57) 4104.57,1059.57 4128.13,1083.13 4276.97,1083.13 4324.51,1035.59 4324.51,979.58 4486.4,817.69 4693.5,817.69 4825.28,685.92 4904.38,685.92 4980.76,609.55 v1(5058.86,609.55)
AM263_ICSSM_MII1_RXD2: U1.E17 U50.37 | length 1527
  Top Layer w4: U1.E17@3901.07,1106.81 3916.82,1122.56 3951.95,1122.56 3963.62,1134.23 3964.06,1134.23
  Top Layer w5.3: 3964.06,1134.23 4008.05,1134.23 4060.42,1186.6 4100.64,1186.6 4129.36,1157.88 4230.94,1157.88 4241.37,1168.31 4283.27,1168.31 4310,1141.58 v1(4310,1121.09) ; v1(4981.77,732.24) U50.37@5023.43,732.24
  SIG 1 w4.75: v1(4310,1121.09) 4310,1114.54 4576.7,847.84 4710.42,847.84 4840.73,717.53 4920.26,717.53 4977.8,660 5008.56,660 5016.28,667.72 5016.28,718.95 5002.99,732.24 v1(4981.77,732.24)
AM263_ICSSM_MII1_RXD3: U1.E18 U50.35 | length 1529
  Top Layer w4: U1.E18@3932.57,1106.81 3954.96,1106.81
  Top Layer w5.3: 3954.96,1106.81 3971.72,1123.58 4021.45,1123.58 4042.97,1145.1 v1(4273.69,1145.1) ; v1(4981.77,771.61) U50.35@5023.43,771.61
  SIG 1 w4.75: v1(4273.69,1145.1) 4313.21,1145.1 4477.76,980.55 4477.76,963.02 4582.9,857.89 4714.58,857.89 4820.98,751.49 5007.7,751.49 5030,729.19 5030,703.61 5038.61,695 5058.86,695 5063.86,700 5063.86,725 5017.25,771.61 v1(4981.77,771.61)
AM263_ICSSM_MII1_RXDV: U1.F16 U50.33 | length 1526.7
  Top Layer w5.3: v1(4981.16,810.98) U50.33@5023.43,810.98
  Top Layer w10: U1.F16@3869.57,1075.32 v1(3885.32,1091.06)
  SIG 1 w4.75: v1(3885.32,1091.06) 3891.58,1084.81 4016.03,1084.81 4030,1098.78 4030,1109.38 4043.93,1123.3 4115,1123.3 4135.64,1143.95 4234.05,1143.95 4254.45,1164.35 4312.72,1164.35 4489.95,987.12 4489.95,965.05 4587.06,867.94 4829.18,867.94 4866.02,831.1 4992.47,831.1 5000.41,839.04 5000.41,860.7 5009.71,870 5023.32,870 5027.73,865.59 5027.73,819.09 5019.62,810.98 v1(4981.16,810.98)
AM263_ICSSM_MII1_RXER: R111.1 R123.2 R229.2 U1.F15 U22.46 | length 3845.8
  Top Layer w5.3: v1(6545,740) 6590,740 6601.09,751.09 6639.71,751.09 6645,756.38 6645,774.79 R111.1@6646.28,776.06 R123.2@6698,776.06 v1(6698,738.56)
  Top Layer w10: U1.F15@3838.08,1075.32 v1(3853.83,1091.06)
  SIG 1 w4.75: v1(3853.83,1091.06) 3869.95,1074.94 3898.81,1074.94 3901.93,1071.82 4098.36,1071.82 4152.6,1126.07 4265.5,1126.07 4265.71,1125.85 4272.39,1125.85 4410.42,987.83 4410.42,925.24 4497.86,837.79 4701.83,837.79 4833.6,706.02 4912.71,706.02 4970.89,647.83 5087.16,647.83 5119.65,615.35 5163.96,615.35 5229.14,550.16 5237.2,550.16 5237.47,549.89 5382.98,549.89 5398.65,565.56 5459.65,565.56 5486.35,538.86 5598.88,538.86 5663.88,473.85 5847.89,473.85 5963.51,358.23 6383.47,358.23 6469.77,444.53 6627.57,444.53 6698,514.96 v1(6698,738.56)
  Bottom Layer w5.3: U22.46@6544.07,703.9 6544.07,739.07 v1(6545,740) ; R229.2@6696.59,777.98 6696.59,739.97 v1(6698,738.56)
AM263_ICSSM_MII1_RXLINK: R110.1 R122.2 R227.2 U1.D18 U22.47 | length 4713.3
  Top Layer w5.3: U1.D18@3932.57,1138.31 3950.01,1138.31 3959.25,1147.55 3996.88,1147.55 4064.83,1215.5 4240.53,1215.5 4273.28,1248.25 4273.28,1558.76 4323.56,1609.05 4663.05,1609.05 4706.96,1652.96 4961.16,1652.96 5062.92,1551.21 5229.48,1551.21 5472.67,1794.4 6426.79,1794.4 6542.39,1910 v1(6660,1910) ; R110.1@6579.39,776.46 v1(6605,776.46)
  SIG 1 w4.75: v1(6660,1910) 6653.55,1903.55 6653.55,1829.56 6665.53,1817.58 6665.53,1780 6652.89,1767.36 6652.89,1718.09 6689.95,1681.03 6689.95,922.44 v1(6696.59,915.8)
  Bottom Layer w5.3: U22.47@6563.76,703.9 6563.76,729.37 6579.39,745 R122.2@6579.39,776.46 v1(6605,776.46) 6635,806.46 6635,837.75 6612.73,860.01 R227.2@6612.73,915.31 6696.11,915.31 v1(6696.59,915.8)
AM263_ICSSM_MII1_TXCLK: R86.1 U50.18 | length 1682.6
  Top Layer w5.3: R86.1@3951,1502.17 3951,1527.56 v1(3952.91,1529.47) ; v1(5098.23,1130.53) 5117.91,1110.84 U50.18@5117.91,1043.26
  SIG 1 w4.75: v1(3952.91,1529.47) 3952.91,1509.47 4131.77,1330.6 4231.74,1330.6 4593.17,969.17 4679.89,969.17 4770.61,1059.9 4931.16,1059.9 4966.35,1024.72 4966.35,998.25 4979.62,984.98 4996.3,984.98 5010,998.68 5010,1040.61 5098.23,1128.84 v1(5098.23,1130.53)
AM263_ICSSM_MII1_TXCLK_R: R86.2 U1.C16 | length 335
  Top Layer w5.3: R86.2@3951,1462.8 3951,1444.73 v1(3961,1434.73)
  Top Layer w10: U1.C16@3869.57,1169.8 v1(3885.32,1185.55)
  SIG 1 w4.75: v1(3885.32,1185.55) 3885.32,1359.06 v1(3961,1434.73)
AM263_ICSSM_MII1_TXD0: R81.1 U50.28 | length 1780.2
  Top Layer w5.3: R81.1@4181.94,1300.76 v1(4210,1300.76) ; v1(4936.77,889.72) 4937.15,890.1 4953.84,890.1 4973.15,909.41 U50.28@5023.43,909.41
  SIG 1 w4.75: v1(4210,1300.76) 4069.24,1300.76 4062.43,1307.56 4062.43,1347.14 4057,1352.56 3924.06,1352.56 3907.53,1336.04 3907.53,1264.29 3907.53,1244.67 3927.95,1224.25 3964.06,1224.25 4130.76,1224.25 4150.52,1204.49 4150.52,1172.3 4158.78,1164.05 4225.72,1164.05 4246.13,1184.45 4321.04,1184.45 4578.5,927 4629.38,927 4657.3,899.09 4927.41,899.09 v1(4936.77,889.72)
AM263_ICSSM_MII1_TXD0_R: R81.2 U1.B18 | length 251.2
  Top Layer w5.3: U1.B18@3932.57,1201.3 3958.55,1227.29 4009.8,1227.29 4083.26,1300.76 R81.2@4142.57,1300.76
AM263_ICSSM_MII1_TXD1: R82.1 U50.26 | length 1695.2
  Top Layer w5.3: R82.1@4037,1502.17 v1(4037,1530.23) ; v1(4936.77,929.09) 4954.16,929.09 4973.85,948.78 U50.26@5023.43,948.78
  SIG 1 w4.75: v1(4037,1530.23) 4017.75,1549.48 3914.74,1549.48 3905.78,1540.51 3905.78,1526.73 4112.23,1320.28 4222.54,1320.28 4273.98,1268.84 4279.3,1268.84 4589.01,959.12 4689.14,959.12 4759.94,1029.92 4942.29,1029.92 4956.3,1015.92 4956.3,948.62 v1(4936.77,929.09)
AM263_ICSSM_MII1_TXD1_R: R82.2 U1.B17 | length 340.1
  Top Layer w4: U1.B17@3901.07,1201.3 3918.69,1218.92 3918.69,1242.52 3926.15,1249.98
  Top Layer w5.3: 3926.15,1249.98 3940.36,1264.19 3951.39,1264.19 4056.16,1368.97 4056.16,1421.67 4037,1440.83 R82.2@4037,1462.8
AM263_ICSSM_MII1_TXD2: R83.1 U50.24 | length 1710.2
  Top Layer w5.3: R83.1@4189.94,1194.45 4206.6,1194.45 v1(4217.75,1183.3) ; v1(4936.77,968.46) 4960.31,968.46 4980,988.15 U50.24@5023.43,988.15
  SIG 1 w4.75: v1(4217.75,1183.3) 4170.82,1183.3 4163.29,1190.83 4163.29,1205.93 4134.87,1234.35 4023.89,1234.35 3983.49,1274.75 3970.05,1274.75 3965.9,1278.9 3965.9,1300.93 3970.25,1305.28 4020.8,1305.28 4025,1301.08 4025,1274.85 4027.78,1272.07 4043.93,1272.07 4047.68,1275.82 4047.68,1287.84 4050.46,1290.63 4129.81,1290.63 4132.6,1287.84 4132.6,1279.73 4129.81,1276.95 4105.98,1276.95 4102.56,1273.53 4102.56,1262.14 4105.44,1259.27 4135.73,1259.27 4190.2,1204.8 4314.91,1204.8 4582.04,937.67 4711.76,937.67 4759.09,985 4920.23,985 v1(4936.77,968.46)
AM263_ICSSM_MII1_TXD2_R: R83.2 U1.D16 | length 304.6
  Top Layer w5.3: v1(4122.16,1194.87) 4150.15,1194.87 R83.2@4150.57,1194.45
  Top Layer w10: U1.D16@3869.57,1138.31 v1(3885.32,1154.06)
  SIG 1 w4.75: v1(3885.32,1154.06) 3926.13,1194.87 v1(4122.16,1194.87)
AM263_ICSSM_MII1_TXD3: R84.1 U50.22 | length 1753.5
  Top Layer w5.3: R84.1@4181.94,1265.85 4201.47,1265.85 4206.56,1260.76 v1(4210,1260.76) ; v1(4936.77,1007.83) 4935.33,1007.83 4927.32,999.82 4903.71,999.82 4898.37,1005.16 4898.37,1029.23 4910,1040.86 4910,1071.77 4913.53,1075.3 4933.67,1075.3 4936.77,1072.19 4936.77,1036.62 4944.7,1028.69 4952.75,1028.69 4958.69,1034.63 4958.69,1076.47 4962.72,1080.49 5002.97,1080.49 5006.07,1077.39 5006.07,1065.34 5002.97,1062.23 4995.45,1062.23 4990,1056.78 4990,1032.52 4995,1027.52 U50.22@5023.43,1027.52
  SIG 1 w4.75: v1(4210,1260.76) 4210,1240.84 4216.49,1234.35 4232.1,1234.35 4236.47,1238.71 4236.47,1255.96 ; 4236.49,1255.98 4236.49,1276.18 4232.66,1280 4151.19,1280 4143.86,1272.67 4143.86,1265.35 4194.21,1215 4252.22,1215 4255,1217.78 4255,1255.86 4257.92,1258.79 4275.13,1258.79 4281.67,1252.25 4281.67,1220.87 4287.69,1214.85 4319.07,1214.85 4323.89,1210.03 4584.85,949.07 4708.95,949.07 4762.39,1002.51 4762.39,1015.47 4766.79,1019.87 4778.94,1019.87 4782.42,1016.39 4782.42,1002.63 4788.17,996.88 4809.56,996.88 4813.82,1001.14 4813.82,1016.39 4817.3,1019.87 4832.03,1019.87 4835,1016.9 4835,1000.05 4840,995.05 4860,995.05 4864.57,999.62 4864.57,1016.03 4867.87,1019.32 4887.22,1019.32 4890,1016.54 4890,1000.05 4895,995.05 4923.99,995.05 v1(4936.77,1007.83)
AM263_ICSSM_MII1_TXD3_R: R84.2 U1.C17 | length 281.3
  Top Layer w5.3: U1.C17@3901.07,1169.8 3918.04,1186.78 3938.58,1186.78 3968.11,1216.3 4016.29,1216.3 4051.6,1251.61 4100.27,1251.61 4114.5,1265.85 R84.2@4142.57,1265.85
AM263_ICSSM_MII1_TXEN: R85.1 U50.20 | length 1708.7
  Top Layer w5.3: R85.1@3999,1502.17 v1(3999,1530.23) ; v1(5058.86,1140.74) 5058.86,1114.69 5078.54,1095 U50.20@5078.54,1043.26
  SIG 1 w4.75: v1(3999,1530.23) 3999,1510.23 4059.95,1449.28 4059.95,1448.74 4168.04,1340.65 4257.8,1340.65 4351.65,1246.81 4377.54,1246.81 4415.05,1209.3 4415.05,1166.93 4601.88,980.11 4665.89,980.11 4755.73,1069.95 4935.33,1069.95 4945.23,1060.05 4961.68,1060.05 4966.23,1064.6 4966.23,1141.23 4974.45,1149.45 4995.55,1149.45 5004.88,1140.12 5004.88,1071.62 5011.5,1065 5018.49,1065 5058.86,1105.37 v1(5058.86,1140.74)
AM263_ICSSM_MII1_TXEN_R: R85.2 U1.A17 | length 324.5
  Top Layer w5.3: U1.A17@3901.07,1232.8 3901.07,1237.13 3915.55,1251.61 3915.55,1293.56 3926.22,1304.23 3970.29,1304.23 4032.98,1366.92 4032.98,1405.62 3999,1439.6 R85.2@3999,1462.8
AM263_IEP0_EDC_SYNC_OUT0: J6/J8.72 R88.1 | length 863.7
  Bottom Layer w5.3: R88.1@3948.66,1662.24 3950.63,1662.24 3957.82,1669.44 3957.82,1671.4 3996.93,1710.51 4664.68,1710.51 J6/J8.72@4754.17,1800
AM263_IEP0_EDC_SYNC_OUT0_R: R88.2 U1.D15 | length 563.4
  Top Layer w10: U1.D15@3838.08,1138.31 v1(3853.83,1154.06)
  SIG 1 w4.75: v1(3853.83,1154.06) 3869.2,1169.43 3869.2,1632.86 3880.61,1644.26 v1(3880.61,1646.49)
  Bottom Layer w5.3: v1(3880.61,1646.49) 3883.04,1648.92 3883.04,1653.07 3892.22,1662.24 R88.2@3909.29,1662.24
AM263_IEP0_EDIO_DATA_IN_OUT31: J6/J8.71 R87.1 | length 981.5
  Bottom Layer w5.3: R87.1@3948.66,1619.24 3950.63,1619.24 3957.82,1626.44 3957.82,1628.4 4028.94,1699.52 4753.7,1699.52 J6/J8.71@4854.17,1800
AM263_IEP0_EDIO_DATA_IN_OUT31_R: R87.2 U1.C15 | length 616.8
  Top Layer w10: U1.C15@3838.08,1169.8 v1(3853.83,1185.55)
  SIG 1 w4.75: v1(3849.3,1672.34) 3849.3,1633.93 3855.24,1627.98 3855.24,1186.97 v1(3853.83,1185.55)
  Bottom Layer w5.3: v1(3849.3,1672.34) 3849.3,1633.54 3863.6,1619.24 R87.2@3909.29,1619.24
AM263_INT1_PB_GPIO123: U1.D14 U34.4 | length 4591
  Top Layer w4: v1(471.55,1965.47) U34.4@501.22,1965.47
  Top Layer w5.3: v1(3594.29,1660.39) 3658.3,1660.39 3719.54,1721.62 3834.67,1721.62 3841.5,1714.79 3866.58,1714.79 v1(3869.01,1712.36)
  Top Layer w10: U1.D14@3806.58,1138.31 v1(3822.33,1154.06)
  SIG 1 w4.75: v1(471.55,1965.47) 470.75,1964.67 470.75,1817.65 505.43,1782.98 554.91,1782.98 576.78,1804.85 698.11,1804.85 702.86,1800.1 948.52,1800.1 972.87,1775.75 1018.51,1775.75 1060.41,1817.65 1087.15,1817.65 1190,1920.5 1265,1920.5 1307,1878.5 1307,1789.5 1333,1763.5 1385.02,1763.5 1470,1678.52 1734.51,1678.52 1768.04,1645 2106.51,1645 2176.17,1714.66 2390.48,1714.66 2437.88,1762.07 3094.73,1762.07 3111.64,1745.15 3534.85,1745.15 3594.29,1685.71 v1(3594.29,1660.39) ; v1(3822.33,1154.06) 3837.71,1169.43 3837.71,1396.21 3843.66,1402.16 3843.66,1625.35 3830.05,1638.96 3830.05,1685.95 3856.09,1711.99 3868.64,1711.99 v1(3869.01,1712.36)
AM263_LED_ENABLE_GPIO25: R278.2 U1.C7 U48.8 | length 2011.2
  Top Layer w5.3: U48.8@2117.28,1645 R278.2@2211.38,1645 v1(2211.38,1675)
  Top Layer w10: v1(3570.36,1185.55) U1.C7@3586.11,1169.8
  SIG 1 w4.75: v1(2211.38,1675) 2397.62,1675 2454.54,1731.92 3082.22,1731.92 3099.14,1715 3462.11,1715 3543.94,1633.18 3543.94,1524.39 3537.75,1518.2 3537.75,1502.26 3575.31,1464.7 3575.31,1194.09 3570.36,1189.14 v1(3570.36,1185.55)
AM263_LED_GPIO26: R303.1 R304.2 U1.B7 | length 2816.2
  Top Layer w4: 3568.25,1264.29 3568.49,1264.06 3568.49,1218.92 U1.B7@3586.11,1201.3
  Top Layer w5.3: v1(3549.99,1668.56) 3549.99,1611.2 3547.96,1609.17 3547.96,1557.69 3577.37,1528.28 3577.37,1352.62 3565.65,1340.9 3565.65,1266.89 3568.25,1264.29 ; v1(5512,1882.26) R304.2@5545.31,1882.26 R303.1@5545.31,1940.86
  Bottom Layer w5.3: v1(3549.99,1668.56) 3586.4,1632.15 3633.22,1632.15 3648.7,1647.63 3693.39,1647.63 3733.82,1688.06 3777.74,1688.06 3824.4,1641.4 3824.4,1618.74 3854.86,1588.28 3969.22,1588.28 3987.54,1606.59 3987.54,1628.14 4034.4,1675 4952.5,1675 5045.5,1768 5468.43,1768 5512,1811.58 v1(5512,1882.26)
AM263_LIN1_RXD: U1.A9 U52.33 | length 1931.6
  Top Layer w4: 3647.83,1264.29 3647.83,1234.07 U1.A9@3649.1,1232.8
  Top Layer w5.3: 3647.83,1264.29 3647.83,1333.15 3701.19,1386.5 3701.19,1412.07 3683.68,1429.58 3683.68,1526.74 v1(3663.75,1546.67) ; v1(4258.39,441.26) 4278.07,460.95 U52.33@4350.04,460.94
  Bottom Layer w5.3: v1(3663.75,1546.67) 3644,1526.92 3644,1492.5 3687.33,1449.17 3770.87,1449.17 3905,1315.05 3905,1245.29 3948.74,1201.55 3948.74,734.03 3977.54,705.24 3994.63,705.24 4063.89,635.98 4153.99,635.98 4202.38,587.59 4202.38,528.16 4217.75,512.79 4217.75,481.9 v1(4258.39,441.26)
AM263_LIN1_TXD: R297.1 U52.31 | length 1517.9
  Top Layer w5.3: R297.1@3661,1482.61 3661,1504.23 3664,1507.23 v1(3664,1510.67) ; v1(4258.39,480.63) 4278.07,500.32 U52.31@4350.04,500.32
  Bottom Layer w5.3: v1(3664,1510.67) 3664,1493 3691.88,1465.12 3769.92,1465.12 3920,1315.04 3920,1248.79 3960.29,1208.51 3960.29,739.4 3979.21,720.48 3997.16,720.48 4069.86,647.78 4157.19,647.78 4244.05,560.92 4244.05,533.88 4238.25,528.09 4238.25,500.19 4257.81,480.63 v1(4258.39,480.63)
AM263_LIN1_TXD_R: R297.2 U1.B9 | length 259.9
  Top Layer w4: 3633.35,1264.29 3633.35,1217.05 U1.B9@3649.1,1201.3
  Top Layer w5.3: 3633.35,1264.29 3633.35,1268.8 3636.5,1271.94 3636.5,1342.41 3659.52,1365.44 3659.52,1441.76 R297.2@3661,1443.24
AM263_LIN2_RXD: U1.B8 U52.41 | length 3539
  Top Layer w4: 3601.86,1230 3601.86,1217.05 U1.B8@3617.61,1201.3
  Top Layer w5.3: 3601.86,1230 3601.86,1272.06 3586.85,1287.07 3586.85,1328.36 3602.63,1344.14 3602.63,1521.63 v1(3663.67,1582.67) ; U52.41@4424.84,346.77 4424.84,301.2 4435.49,290.55 v1(4435.49,290)
  Bottom Layer w5.3: v1(3663.67,1582.67) 3686,1560.34 3686,1499.5 3708.59,1476.91 3773.12,1476.91 3846.75,1403.28 4025.98,1403.28 4089.53,1339.72 4352.96,1339.72 4391.67,1378.43 4391.67,1464.81 4425.66,1498.8 4487.24,1498.8 4497.46,1488.58 4817.14,1488.58 4853.34,1452.38 4853.34,1443.17 4984.52,1311.99 4984.52,935.62 5001.3,918.85 5001.3,724.15 4970.21,693.07 4970.21,622.23 4621.6,273.62 4451.87,273.62 v1(4435.49,290)
AM263_LIN2_RXD_PR0_PRU0_GPIO11: J5/J7.43 U52.2 | length 638.1
  Top Layer w5.3: U52.2@4479.96,382.2 4541.22,382.2 4555,368.43 4555,340.59 v1(4555.59,340)
  Bottom Layer w5.3: J5/J7.43@4154.17,100 4205,150.83 4268.22,150.83 4307.78,190.39 4307.78,237.87 4409.9,340 v1(4555.59,340)
AM263_LIN2_TXD: R166.1 U52.39 | length 1767.1
  Top Layer w5.3: R166.1@3623,1482.17 v1(3623,1510.23) ; v1(4294.77,298.84) 4295.11,298.5 4369.71,298.5 4385.47,314.27 U52.39@4385.47,346.77
  Bottom Layer w5.3: v1(3623,1510.23) 3623,1488 3672.43,1438.57 3766.48,1438.57 3890,1315.06 3890,1241.51 3937.63,1193.88 3937.63,727.37 3970.38,694.62 3990.26,694.62 4059.5,625.38 4149.6,625.38 4191.78,583.2 4191.78,523.77 4204.1,511.45 4204.1,468.33 4242.45,429.98 ccw(c4258.39,441.26) 4247.1,425.33 4286.23,386.19 4286.23,348.51 4294.77,339.97 v1(4294.77,298.84)
AM263_LIN2_TXD_PR0_PRU0_GPIO9: J5/J7.44 U52.3 | length 666.9
  Top Layer w5.3: U52.3@4479.96,401.89 4550.67,401.89 4592.56,360 v1(4592.56,340.87)
  Bottom Layer w5.3: J5/J7.44@4254.17,100 4299.17,145 4385.31,145 4408.86,168.54 4408.86,304.51 4422.72,318.37 4570.06,318.37 v1(4592.56,340.87)
AM263_LIN2_TXD_R: R166.2 U1.A8 | length 216.7
  Top Layer w4: U1.A8@3617.61,1232.8 3617.61,1264.29
  Top Layer w5.3: 3617.61,1264.29 3617.61,1268.04 3625.9,1276.33 3625.9,1331.99 3620.48,1337.41 3620.48,1440.27 R166.2@3623,1442.8
AM263_MCAN0_RX: R249.1 U1.M1 | length 8009
  Top Layer w5.3: U1.M1@3397.13,886.34 3387.57,886.34 3365.01,863.78 3122.76,863.78 3098.41,839.43 2971.84,839.43 2928.22,795.81 2875.74,795.81 2829.75,841.8 2829.75,1096.34 2806.08,1120.01 2806.08,1148.09 2850,1192 2850,1295.92 2966.47,1412.39 2966.47,1743.41 3150,1926.94 3150,1949.44 3305.44,2104.89 4630.13,2104.89 4661.93,2073.09 5042.35,2073.09 5074.15,2104.89 6635.11,2104.89 v1(6655,2085)
  SIG 1 w4.75: v1(6655,2085) 6627.03,2057.03 6627.03,1801.63 6642.84,1785.82 6642.84,1713.93 6650.05,1706.72 6650.05,1643.84 6640.75,1634.54 6640.75,1462.85 6645.75,1457.85 6645.75,1102.32 6593.49,1050.06 6593.49,960.67 6665.53,888.63 6665.53,834.47 6814.3,685.7 6814.3,240.66 6904.96,150 7035.73,150 7088.93,96.79 7088.93,-2.48 v1(7100,-13.54)
  Bottom Layer w5.3: R249.1@7069.69,-88.54 7069.69,-70.32 7100,-40 v1(7100,-13.54)
AM263_MCAN0_TX: R167.1 R245.1 | length 7277.7
  Top Layer w5.3: R167.1@3040,874.38 2984.37,874.38 2971.57,861.58 2882.47,861.58 2840.35,903.69 2840.35,1119.87 2860.6,1140.12 2860.6,1291.52 2977.1,1408.02 2977.1,1739.05 3160.6,1922.55 3160.6,1945.05 3309.83,2094.29 4624.06,2094.29 4658.95,2059.39 5043.64,2059.39 5078.54,2094.29 6590.71,2094.29 v1(6600,2085)
  SIG 1 w4.75: v1(6600,2085) 6600,1814.45 6632.79,1781.66 6632.79,1709.76 6640,1702.55 6640,1648 6630.7,1638.7 6630.7,1458.69 6635.7,1453.69 6635.7,1106.49 6583.44,1054.22 6583.44,951.56 6627.03,907.97 6627.03,851.63 6804.25,674.41 6804.25,220.75 6936.18,88.82 v1(7069.69,88.82)
  Bottom Layer w5.3: R245.1@7069.69,61.46 v1(7069.69,88.82)
AM263_MCAN0_TX_R: R167.2 U1.L1 | length 336.7
  Top Layer w5.3: R167.2@3079.37,874.38 3081.34,874.38 3088.53,881.57 3088.53,883.16 3091.64,886.27 3351.27,886.27 3382.83,917.83 U1.L1@3397.13,917.83
AM263_MCAN1_RX: U1.L2 U52.37 | length 2854.1
  Top Layer w4: 3395,902.09 3412.88,902.09 U1.L2@3428.63,917.83
  Top Layer w5.3: v1(2884.25,815.34) 2918.94,850.03 3092.98,850.03 3118.25,875.3 3360.37,875.3 3387.16,902.09 3395,902.09 ; v1(4114.05,419.48) 4130.2,419.48 4167.47,382.2 U52.37@4350.04,382.2
  Bottom Layer w5.3: v1(2884.25,815.34) 2830,815.34 2789.88,775.21 2789.88,456.54 2819.86,426.56 3041.82,426.56 3082.74,385.63 3171.8,385.63 3265.09,292.34 3265.09,259.63 3278.2,246.52 3385.71,246.52 3408.73,223.5 3481.75,223.5 3501.79,203.46 3627.71,203.46 3686.26,144.9 3727.28,144.9 3828.99,246.61 3867.5,246.61 3969.1,348.22 4042.79,348.22 v1(4114.05,419.48)
AM263_MCAN1_TX: R168.1 U52.35 | length 2372.8
  Top Layer w5.3: v1(3011.94,922.38) R168.1@3040,922.38 ; v1(4114.05,455.48) 4147.95,421.57 U52.35@4350.04,421.57
  Bottom Layer w5.3: v1(3011.94,922.38) 3011.94,790.14 2976.83,755.04 2956.91,755.04 2800.48,598.6 2800.48,463.16 2823.72,439.92 3043.45,439.92 3082.98,400.38 3171.4,400.38 3175.55,396.23 3176.19,396.23 3275.69,296.73 3275.69,296.1 3284.15,287.64 3342,287.64 3371.82,257.81 3392.16,257.81 3415.47,234.5 3486.72,234.5 3504.43,216.79 3639.76,216.79 3665.52,191.03 3745.77,191.03 3811.95,257.21 3863.1,257.21 3969.61,363.71 4022.28,363.71 v1(4114.05,455.48)
AM263_MCAN1_TX_R: R168.2 U1.K1 | length 328.9
  Top Layer w4: 3365.64,949.33 U1.K1@3397.13,949.33
  Top Layer w5.3: R168.2@3079.37,922.38 3106.32,949.33 3365.64,949.33
AM263_MDIO0_MDC: R61.1 R63.1 U17.9 | length 125.7
  Bottom Layer w5.3: U17.9@4705.28,874.06 4780.59,874.06 R63.1@4785.59,869.06 R61.1@4785.59,825.79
